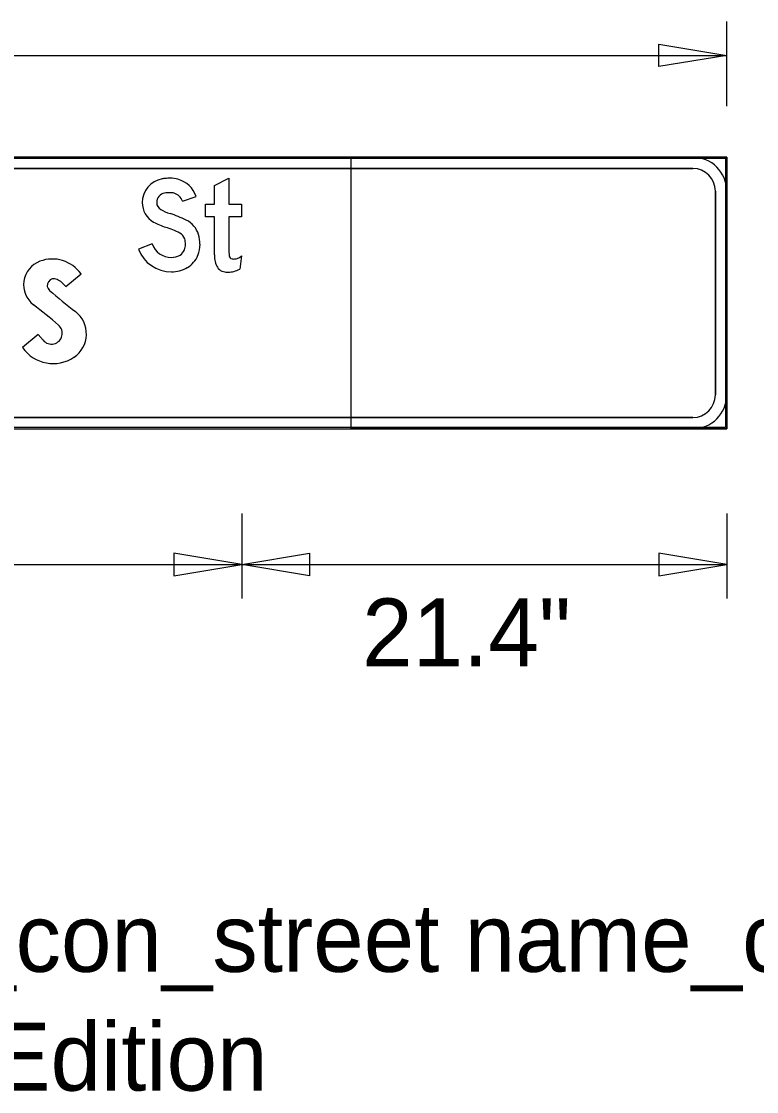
# Model space of a CAD drawing. Extents: x 1708.4 to 1771.6, y 238.3 to 283.4.
# Drawn here: x 1762.041 to 1765.29, y 273.303 to 278.033 of the extents above; entities that cross this region are included whole.
import ezdxf

# ---------------------------------------------------------------- set-up
doc = ezdxf.new("R2010")
doc.units = 0
for name, color, linetype in [('Level 11', 7, 'Continuous'), ('Level 2', 7, 'Continuous'), ('Level 3', 7, 'Continuous'), ('Level 4', 7, 'Continuous'), ('Level 5', 7, 'Continuous')]:
    doc.layers.add(name, color=color, linetype=linetype)

msp = doc.modelspace()

# ---------------------------------------------------------------- linework, layer by layer
at = {"layer": 'Level 11'}
msp.add_lwpolyline([(1763.4978, 277.433), (1765.1581, 277.433), (1765.1581, 276.233), (1763.4978, 276.233)], close=True, dxfattribs=at)
at = {"layer": 'Level 2'}
for p, q in [((1765.1582, 277.433), (1758.558, 277.433)), ((1765.1582, 277.433), (1758.558, 277.433)), ((1765.0083, 277.433), (1758.708, 277.433)), ((1765.1582, 276.2328), (1765.1582, 277.433)), ((1765.1582, 276.2328), (1765.1582, 277.433)), ((1758.563, 277.428), (1765.1533, 277.428)), ((1765.1533, 277.428), (1765.1533, 276.2378)), ((1758.708, 277.383), (1765.0083, 277.383)), ((1765.1082, 277.283), (1765.1082, 276.3827)), ((1765.1582, 276.3827), (1765.1582, 277.283)), ((1763.0141, 276.997), (1763.0056, 276.9377)), ((1762.2369, 276.8615), (1762.3047, 276.9168)), ((1765.0083, 276.2828), (1758.7085, 276.2828)), ((1765.1533, 276.2378), (1758.558, 276.2378)), ((1758.558, 276.2328), (1765.1582, 276.2328)), ((1758.558, 276.2328), (1765.1582, 276.2328)), ((1758.7085, 276.2328), (1765.0083, 276.2328))]:
    msp.add_line(p, q, dxfattribs=at)
for points in [[(1762.8941, 277.0012), (1762.8941, 277.169), (1762.8541, 277.169), (1762.8541, 277.225), (1762.8941, 277.225), (1762.8941, 277.3081), (1762.9581, 277.34), (1762.9581, 277.225), (1763.0141, 277.225), (1763.0141, 277.169), (1762.9581, 277.169), (1762.9581, 277.0111)], [(1762.752, 277.2388), (1762.8127, 277.259)], [(1762.618, 277.0493), (1762.5581, 277.0267)], [(1762.1366, 276.6236), (1762.1147, 276.6494), (1762.0461, 276.5912)]]:
    msp.add_lwpolyline(points, dxfattribs=at)
for centre, radius, start, end in [((1765.0083, 277.283), 0.15, 0, 90), ((1765.0083, 277.283), 0.1, 0, 90), ((1762.1613, 276.8691), 0.111, 110.6886, 232.5524), ((1762.1772, 276.827), 0.156, 35.1637, 110.6886), ((1762.1847, 276.8662), 0.03, 63.5708, 229.2183), ((1762.1473, 276.791), 0.114, 38.1969, 63.5708), ((1763.7817, 278.7176), 2.475, 229.2183, 232.6246), ((1760.5889, 274.816), 2.475, 49.2471, 52.5524), ((1762.2039, 276.6521), 0.1242, 303.8841, 52.6246), ((1762.1733, 276.6546), 0.048, 220.2627, 49.2471), ((1762.1811, 276.686), 0.165, 215.0547, 303.8841), ((1765.0083, 276.3827), 0.15, 270, 0), ((1765.0083, 276.3827), 0.1, 270, 0)]:
    msp.add_arc(centre, radius, start, end, dxfattribs=at)
for centre, major_axis, ratio, start_param, end_param in [((1762.6929, 277.1662), (0, 0.1735), 0.999995, 0.090794, 0.175685), ((1762.6983, 277.1074), (0, 0.2326), 0.999995, 6.283185, 6.373979), ((1762.6983, 277.2127), (0, 0.1273), 0.999995, 6.012094, 6.283185), ((1762.6812, 277.2321), (0, 0.1066), 0.999995, 0.175685, 1.570796), ((1762.7008, 277.2217), (0, 0.118), 0.999995, 5.034126, 6.012094), ((1762.6812, 277.2321), (0, 0.0426), 0.999995, 0.175685, 1.570796), ((1762.6929, 277.1662), (0, 0.1095), 0.999995, 0.090794, 0.175685), ((1762.6983, 277.1074), (0, 0.1686), 0.999995, 0, 0.090794), ((1762.6983, 277.2127), (0, 0.0633), 0.999995, 6.012094, 6.283185), ((1762.7008, 277.2217), (0, 0.054), 0.999995, 5.034126, 6.012094), ((1762.6733, 277.2321), (0, 0.0986), 0.999995, 1.570796, 2.627164), ((1762.6733, 277.2321), (0, 0.0346), 0.999995, 1.570796, 2.627164), ((1762.7636, 277.392), (0, 0.2182), 0.999995, 2.627164, 2.834816), ((1762.5478, 276.7106), (0, 0.4965), 0.999995, 5.820582, 5.976409), ((1762.7218, 277.0596), (0, 0.1066), 0.999995, 5.010707, 5.820582), ((1762.7636, 277.392), (0, 0.2822), 0.999995, 2.627164, 2.834816), ((1762.5478, 276.7106), (0, 0.4325), 0.999995, 5.820582, 5.976409), ((1762.7218, 277.0596), (0, 0.0426), 0.999995, 5.010707, 5.820582), ((1762.6853, 277.0483), (0, 0.0807), 0.999995, 4.712389, 5.010707), ((1762.6853, 277.0483), (0, 0.1447), 0.999995, 4.712389, 5.010707), ((1762.7037, 277.0816), (0, 0.1556), 0.999995, 1.931277, 3.141593), ((1762.7037, 277.0816), (0, 0.0916), 0.999995, 1.931277, 3.141593), ((1762.7183, 277.0402), (0, 0.0462), 0.999995, 3.672524, 4.331279), ((1762.6979, 277.0483), (0, 0.0682), 0.999995, 4.331279, 4.712389), ((1762.6979, 277.0483), (0, 0.1322), 0.999995, 4.331279, 4.712389), ((1763.0682, 277.0111), (0, 0.1101), 0.999991, 1.570796, 1.695783), ((1762.7037, 277.065), (0, 0.075), 0.999995, 3.141593, 3.672524), ((1762.7183, 277.0402), (0, 0.1102), 0.999995, 3.672524, 4.331279), ((1763.0642, 277.0012), (0, 0.1701), 0.999991, 1.570796, 1.662322), ((1762.9956, 276.994), (0, 0.1012), 0.999991, 1.653079, 1.937165), ((1762.9748, 276.9994), (0, 0.016), 0.999991, 1.695783, 2.93591), ((1762.9796, 277.0224), (0, 0.0395), 0.999991, 2.93591, 3.141593), ((1762.9796, 277.04), (0, 0.0571), 0.999991, 3.141593, 3.322139), ((1762.9845, 277.0133), (0, 0.03), 0.999991, 3.322139, 3.602705), ((1762.9601, 277.0623), (0, 0.0847), 0.999991, 3.602705, 3.831871), ((1762.7037, 277.065), (0, 0.139), 0.999995, 3.141593, 3.672524), ((1762.9521, 276.9772), (0, 0.0545), 0.999991, 1.936133, 2.408497), ((1762.9468, 276.9734), (0, 0.0482), 0.999991, 2.436385, 2.996739), ((1762.9562, 277.1096), (0, 0.1846), 0.999991, 3.052778, 3.141593), ((1762.9562, 277.0333), (0, 0.1083), 0.999991, 3.141593, 3.24959), ((1762.9604, 276.9952), (0, 0.07), 0.999991, 3.24959, 3.420941), ((1762.9326, 277.0921), (0, 0.1708), 0.999991, 3.420942, 3.583276)]:
    msp.add_ellipse(centre, major_axis=major_axis, ratio=ratio, start_param=start_param, end_param=end_param, dxfattribs=at)
at = {"layer": 'Level 3'}
for p, q in [((1765.1582, 277.433), (1758.558, 277.433)), ((1765.0083, 277.433), (1758.708, 277.433)), ((1765.1582, 276.2328), (1765.1582, 277.433)), ((1765.0083, 277.383), (1758.708, 277.383)), ((1765.1082, 276.3827), (1765.1082, 277.283)), ((1765.1582, 276.3827), (1765.1582, 277.283)), ((1763.0141, 276.997), (1763.0056, 276.9377)), ((1762.2369, 276.8615), (1762.3047, 276.9168)), ((1758.708, 276.2828), (1765.0083, 276.2828)), ((1758.558, 276.2328), (1765.1582, 276.2328)), ((1758.708, 276.2328), (1765.0083, 276.2328))]:
    msp.add_line(p, q, dxfattribs=at)
for points in [[(1762.8941, 277.0012), (1762.8941, 277.169), (1762.8541, 277.169), (1762.8541, 277.225), (1762.8941, 277.225), (1762.8941, 277.3081), (1762.9581, 277.34), (1762.9581, 277.225), (1763.0141, 277.225), (1763.0141, 277.169), (1762.9581, 277.169), (1762.9581, 277.0111)], [(1762.752, 277.2388), (1762.8127, 277.259)], [(1762.618, 277.0493), (1762.5581, 277.0267)], [(1762.1366, 276.6236), (1762.1147, 276.6494), (1762.0461, 276.5912)]]:
    msp.add_lwpolyline(points, dxfattribs=at)
for centre, radius, start, end in [((1765.0083, 277.283), 0.15, 0, 90), ((1765.0083, 277.283), 0.1, 0, 90), ((1762.1613, 276.8691), 0.111, 110.6886, 232.5524), ((1762.1772, 276.827), 0.156, 35.1637, 110.6886), ((1762.1847, 276.8662), 0.03, 63.5708, 229.2183), ((1762.1473, 276.791), 0.114, 38.1969, 63.5708), ((1763.7817, 278.7176), 2.475, 229.2183, 232.6246), ((1760.5889, 274.816), 2.475, 49.2471, 52.5524), ((1762.2039, 276.6521), 0.1242, 303.8841, 52.6246), ((1762.1733, 276.6546), 0.048, 220.2627, 49.2471), ((1762.1811, 276.686), 0.165, 215.0547, 303.8841), ((1765.0083, 276.3827), 0.15, 270, 0), ((1765.0083, 276.3827), 0.1, 270, 0)]:
    msp.add_arc(centre, radius, start, end, dxfattribs=at)
for centre, major_axis, ratio, start_param, end_param in [((1762.6929, 277.1662), (0, 0.1735), 0.999995, 0.090794, 0.175685), ((1762.6983, 277.1074), (0, 0.2326), 0.999995, 6.283185, 6.373979), ((1762.6983, 277.2127), (0, 0.1273), 0.999995, 6.012094, 6.283185), ((1762.6812, 277.2321), (0, 0.1066), 0.999995, 0.175685, 1.570796), ((1762.7008, 277.2217), (0, 0.118), 0.999995, 5.034126, 6.012094), ((1762.6812, 277.2321), (0, 0.0426), 0.999995, 0.175685, 1.570796), ((1762.6929, 277.1662), (0, 0.1095), 0.999995, 0.090794, 0.175685), ((1762.6983, 277.1074), (0, 0.1686), 0.999995, 0, 0.090794), ((1762.6983, 277.2127), (0, 0.0633), 0.999995, 6.012094, 6.283185), ((1762.7008, 277.2217), (0, 0.054), 0.999995, 5.034126, 6.012094), ((1762.6733, 277.2321), (0, 0.0986), 0.999995, 1.570796, 2.627164), ((1762.6733, 277.2321), (0, 0.0346), 0.999995, 1.570796, 2.627164), ((1762.7636, 277.392), (0, 0.2182), 0.999995, 2.627164, 2.834816), ((1762.5478, 276.7106), (0, 0.4965), 0.999995, 5.820582, 5.976409), ((1762.7218, 277.0596), (0, 0.1066), 0.999995, 5.010707, 5.820582), ((1762.7636, 277.392), (0, 0.2822), 0.999995, 2.627164, 2.834816), ((1762.5478, 276.7106), (0, 0.4325), 0.999995, 5.820582, 5.976409), ((1762.7218, 277.0596), (0, 0.0426), 0.999995, 5.010707, 5.820582), ((1762.6853, 277.0483), (0, 0.0807), 0.999995, 4.712389, 5.010707), ((1762.6853, 277.0483), (0, 0.1447), 0.999995, 4.712389, 5.010707), ((1762.7037, 277.0816), (0, 0.1556), 0.999995, 1.931277, 3.141593), ((1762.7037, 277.0816), (0, 0.0916), 0.999995, 1.931277, 3.141593), ((1762.7183, 277.0402), (0, 0.0462), 0.999995, 3.672524, 4.331279), ((1762.6979, 277.0483), (0, 0.0682), 0.999995, 4.331279, 4.712389), ((1762.6979, 277.0483), (0, 0.1322), 0.999995, 4.331279, 4.712389), ((1763.0682, 277.0111), (0, 0.1101), 0.999991, 1.570796, 1.695783), ((1762.7037, 277.065), (0, 0.075), 0.999995, 3.141593, 3.672524), ((1762.7183, 277.0402), (0, 0.1102), 0.999995, 3.672524, 4.331279), ((1763.0642, 277.0012), (0, 0.1701), 0.999991, 1.570796, 1.662322), ((1762.9956, 276.994), (0, 0.1012), 0.999991, 1.653079, 1.937165), ((1762.9748, 276.9994), (0, 0.016), 0.999991, 1.695783, 2.93591), ((1762.9796, 277.0224), (0, 0.0395), 0.999991, 2.93591, 3.141593), ((1762.9796, 277.04), (0, 0.0571), 0.999991, 3.141593, 3.322139), ((1762.9845, 277.0133), (0, 0.03), 0.999991, 3.322139, 3.602705), ((1762.9601, 277.0623), (0, 0.0847), 0.999991, 3.602705, 3.831871), ((1762.7037, 277.065), (0, 0.139), 0.999995, 3.141593, 3.672524), ((1762.9521, 276.9772), (0, 0.0545), 0.999991, 1.936133, 2.408497), ((1762.9468, 276.9734), (0, 0.0482), 0.999991, 2.436385, 2.996739), ((1762.9562, 277.1096), (0, 0.1846), 0.999991, 3.052778, 3.141593), ((1762.9562, 277.0333), (0, 0.1083), 0.999991, 3.141593, 3.24959), ((1762.9604, 276.9952), (0, 0.07), 0.999991, 3.24959, 3.420941), ((1762.9326, 277.0921), (0, 0.1708), 0.999991, 3.420942, 3.583276)]:
    msp.add_ellipse(centre, major_axis=major_axis, ratio=ratio, start_param=start_param, end_param=end_param, dxfattribs=at)
at = {"layer": 'Level 4'}
for p, q in [((1765.1582, 277.433), (1758.558, 277.433)), ((1765.0083, 277.433), (1758.708, 277.433)), ((1765.1582, 276.2328), (1765.1582, 277.433)), ((1758.708, 277.383), (1765.0083, 277.383)), ((1765.1082, 277.283), (1765.1082, 276.3827)), ((1765.1582, 276.3827), (1765.1582, 277.283)), ((1763.0141, 276.997), (1763.0056, 276.9377)), ((1762.2369, 276.8615), (1762.3047, 276.9168)), ((1765.0083, 276.2828), (1758.7085, 276.2828)), ((1758.558, 276.2328), (1765.1582, 276.2328)), ((1758.7085, 276.2328), (1765.0083, 276.2328))]:
    msp.add_line(p, q, dxfattribs=at)
for points in [[(1762.8941, 277.0012), (1762.8941, 277.169), (1762.8541, 277.169), (1762.8541, 277.225), (1762.8941, 277.225), (1762.8941, 277.3081), (1762.9581, 277.34), (1762.9581, 277.225), (1763.0141, 277.225), (1763.0141, 277.169), (1762.9581, 277.169), (1762.9581, 277.0111)], [(1762.752, 277.2388), (1762.8127, 277.259)], [(1762.618, 277.0493), (1762.5581, 277.0267)], [(1762.1366, 276.6236), (1762.1147, 276.6494), (1762.0461, 276.5912)]]:
    msp.add_lwpolyline(points, dxfattribs=at)
for centre, radius, start, end in [((1765.0083, 277.283), 0.15, 0, 90), ((1765.0083, 277.283), 0.1, 0, 90), ((1762.1613, 276.8691), 0.111, 110.6886, 232.5524), ((1762.1772, 276.827), 0.156, 35.1637, 110.6886), ((1762.1847, 276.8662), 0.03, 63.5708, 229.2183), ((1762.1473, 276.791), 0.114, 38.1969, 63.5708), ((1763.7817, 278.7176), 2.475, 229.2183, 232.6246), ((1760.5889, 274.816), 2.475, 49.2471, 52.5524), ((1762.2039, 276.6521), 0.1242, 303.8841, 52.6246), ((1762.1733, 276.6546), 0.048, 220.2627, 49.2471), ((1762.1811, 276.686), 0.165, 215.0547, 303.8841), ((1765.0083, 276.3827), 0.15, 270, 0), ((1765.0083, 276.3827), 0.1, 270, 0)]:
    msp.add_arc(centre, radius, start, end, dxfattribs=at)
for centre, major_axis, ratio, start_param, end_param in [((1762.6929, 277.1662), (0, 0.1735), 0.999995, 0.090794, 0.175685), ((1762.6983, 277.1074), (0, 0.2326), 0.999995, 6.283185, 6.373979), ((1762.6983, 277.2127), (0, 0.1273), 0.999995, 6.012094, 6.283185), ((1762.6812, 277.2321), (0, 0.1066), 0.999995, 0.175685, 1.570796), ((1762.7008, 277.2217), (0, 0.118), 0.999995, 5.034126, 6.012094), ((1762.6812, 277.2321), (0, 0.0426), 0.999995, 0.175685, 1.570796), ((1762.6929, 277.1662), (0, 0.1095), 0.999995, 0.090794, 0.175685), ((1762.6983, 277.1074), (0, 0.1686), 0.999995, 0, 0.090794), ((1762.6983, 277.2127), (0, 0.0633), 0.999995, 6.012094, 6.283185), ((1762.7008, 277.2217), (0, 0.054), 0.999995, 5.034126, 6.012094), ((1762.6733, 277.2321), (0, 0.0986), 0.999995, 1.570796, 2.627164), ((1762.6733, 277.2321), (0, 0.0346), 0.999995, 1.570796, 2.627164), ((1762.7636, 277.392), (0, 0.2182), 0.999995, 2.627164, 2.834816), ((1762.5478, 276.7106), (0, 0.4965), 0.999995, 5.820582, 5.976409), ((1762.7218, 277.0596), (0, 0.1066), 0.999995, 5.010707, 5.820582), ((1762.7636, 277.392), (0, 0.2822), 0.999995, 2.627164, 2.834816), ((1762.5478, 276.7106), (0, 0.4325), 0.999995, 5.820582, 5.976409), ((1762.7218, 277.0596), (0, 0.0426), 0.999995, 5.010707, 5.820582), ((1762.6853, 277.0483), (0, 0.0807), 0.999995, 4.712389, 5.010707), ((1762.6853, 277.0483), (0, 0.1447), 0.999995, 4.712389, 5.010707), ((1762.7037, 277.0816), (0, 0.1556), 0.999995, 1.931277, 3.141593), ((1762.7037, 277.0816), (0, 0.0916), 0.999995, 1.931277, 3.141593), ((1762.7183, 277.0402), (0, 0.0462), 0.999995, 3.672524, 4.331279), ((1762.6979, 277.0483), (0, 0.0682), 0.999995, 4.331279, 4.712389), ((1762.6979, 277.0483), (0, 0.1322), 0.999995, 4.331279, 4.712389), ((1763.0682, 277.0111), (0, 0.1101), 0.999991, 1.570796, 1.695783), ((1762.7037, 277.065), (0, 0.075), 0.999995, 3.141593, 3.672524), ((1762.7183, 277.0402), (0, 0.1102), 0.999995, 3.672524, 4.331279), ((1763.0642, 277.0012), (0, 0.1701), 0.999991, 1.570796, 1.662322), ((1762.9956, 276.994), (0, 0.1012), 0.999991, 1.653079, 1.937165), ((1762.9748, 276.9994), (0, 0.016), 0.999991, 1.695783, 2.93591), ((1762.9796, 277.0224), (0, 0.0395), 0.999991, 2.93591, 3.141593), ((1762.9796, 277.04), (0, 0.0571), 0.999991, 3.141593, 3.322139), ((1762.9845, 277.0133), (0, 0.03), 0.999991, 3.322139, 3.602705), ((1762.9601, 277.0623), (0, 0.0847), 0.999991, 3.602705, 3.831871), ((1762.7037, 277.065), (0, 0.139), 0.999995, 3.141593, 3.672524), ((1762.9521, 276.9772), (0, 0.0545), 0.999991, 1.936133, 2.408497), ((1762.9468, 276.9734), (0, 0.0482), 0.999991, 2.436385, 2.996739), ((1762.9562, 277.1096), (0, 0.1846), 0.999991, 3.052778, 3.141593), ((1762.9562, 277.0333), (0, 0.1083), 0.999991, 3.141593, 3.24959), ((1762.9604, 276.9952), (0, 0.07), 0.999991, 3.24959, 3.420941), ((1762.9326, 277.0921), (0, 0.1708), 0.999991, 3.420942, 3.583276)]:
    msp.add_ellipse(centre, major_axis=major_axis, ratio=ratio, start_param=start_param, end_param=end_param, dxfattribs=at)
at = {"layer": 'Level 5'}
for p, q in [((1765.1582, 277.658), (1765.1582, 278.033)), ((1758.558, 277.883), (1765.1582, 277.883)), ((1765.1582, 277.658), (1765.1582, 277.658)), ((1763.0143, 275.8578), (1763.0143, 275.4828)), ((1763.0143, 275.8578), (1763.0143, 275.4828)), ((1765.1582, 275.8578), (1765.1582, 275.4828)), ((1765.1582, 275.8578), (1765.1582, 275.4828)), ((1758.7581, 275.6327), (1763.0143, 275.6327)), ((1763.0143, 275.6327), (1765.1582, 275.6327))]:
    msp.add_line(p, q, dxfattribs=at)
for points in [[(1765.1582, 277.883), (1764.8582, 277.833), (1764.8582, 277.933)], [(1763.0143, 275.6327), (1762.7143, 275.6827), (1762.7143, 275.5828)], [(1763.0143, 275.6327), (1763.3143, 275.6827), (1763.3143, 275.5828)], [(1765.1582, 275.6327), (1764.8582, 275.6827), (1764.8582, 275.5828)]]:
    msp.add_lwpolyline(points, close=True, dxfattribs=at)

# ---------------------------------------------------------------- texts
for s, p in [('21.4"', (1763.547, 275.1827)), ('Panel Style: guide_con_street name_c1_2012.ssi', (1758.558, 273.8328)), ('M.U.T.C.D.:: 2009 Edition', (1758.558, 273.3077))]:
    msp.add_text(s, height=0.3, dxfattribs=at).set_placement(p)

doc.saveas('drawing.dxf')
